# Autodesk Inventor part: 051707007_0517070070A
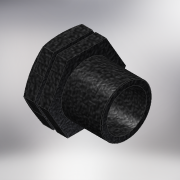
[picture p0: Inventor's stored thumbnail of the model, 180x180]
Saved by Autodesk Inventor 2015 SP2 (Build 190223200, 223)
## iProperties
Created: 2017-05
Part Number: 051707007_0517070070A
Material: Generic
Description: PLASSON PLUG 3/4"
Document SubType Name: Modeling
Designer: Кирилл
Density: 1 g/cm^3
Appearance: Black Cast
Author: Кирилл
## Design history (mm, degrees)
derived "051707.ipt"
feature "Solid1::051707.ipt"
tag "TaggingFeature1"
body "Solid1"
other parameters: "d1" = 26.441, "d2" = 32, "d5" = 17, "d6" = 4.42857, "d8" = 0.31, "d12" = 0, "d14" = 1.47619, "d15" = 31, "d16" = 1.77143, "d17" = 4.42857, "d19" = 0, "d21" = 2.42, "d29" = 0, "H_" = 31, "R_" = 26.441, "E_" = 32, "l_2" = 17, "d20" = 3.66667
